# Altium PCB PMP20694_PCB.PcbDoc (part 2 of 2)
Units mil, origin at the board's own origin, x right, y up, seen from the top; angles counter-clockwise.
Board outline 7086.61 x 2677.17 mil, 2 copper layers (Top Layer, Bottom Layer), stack 62 mil thick; 190 components, 99 nets, 453 pads, 121 vias.
Unrouted connection lines stored in the file: 1.
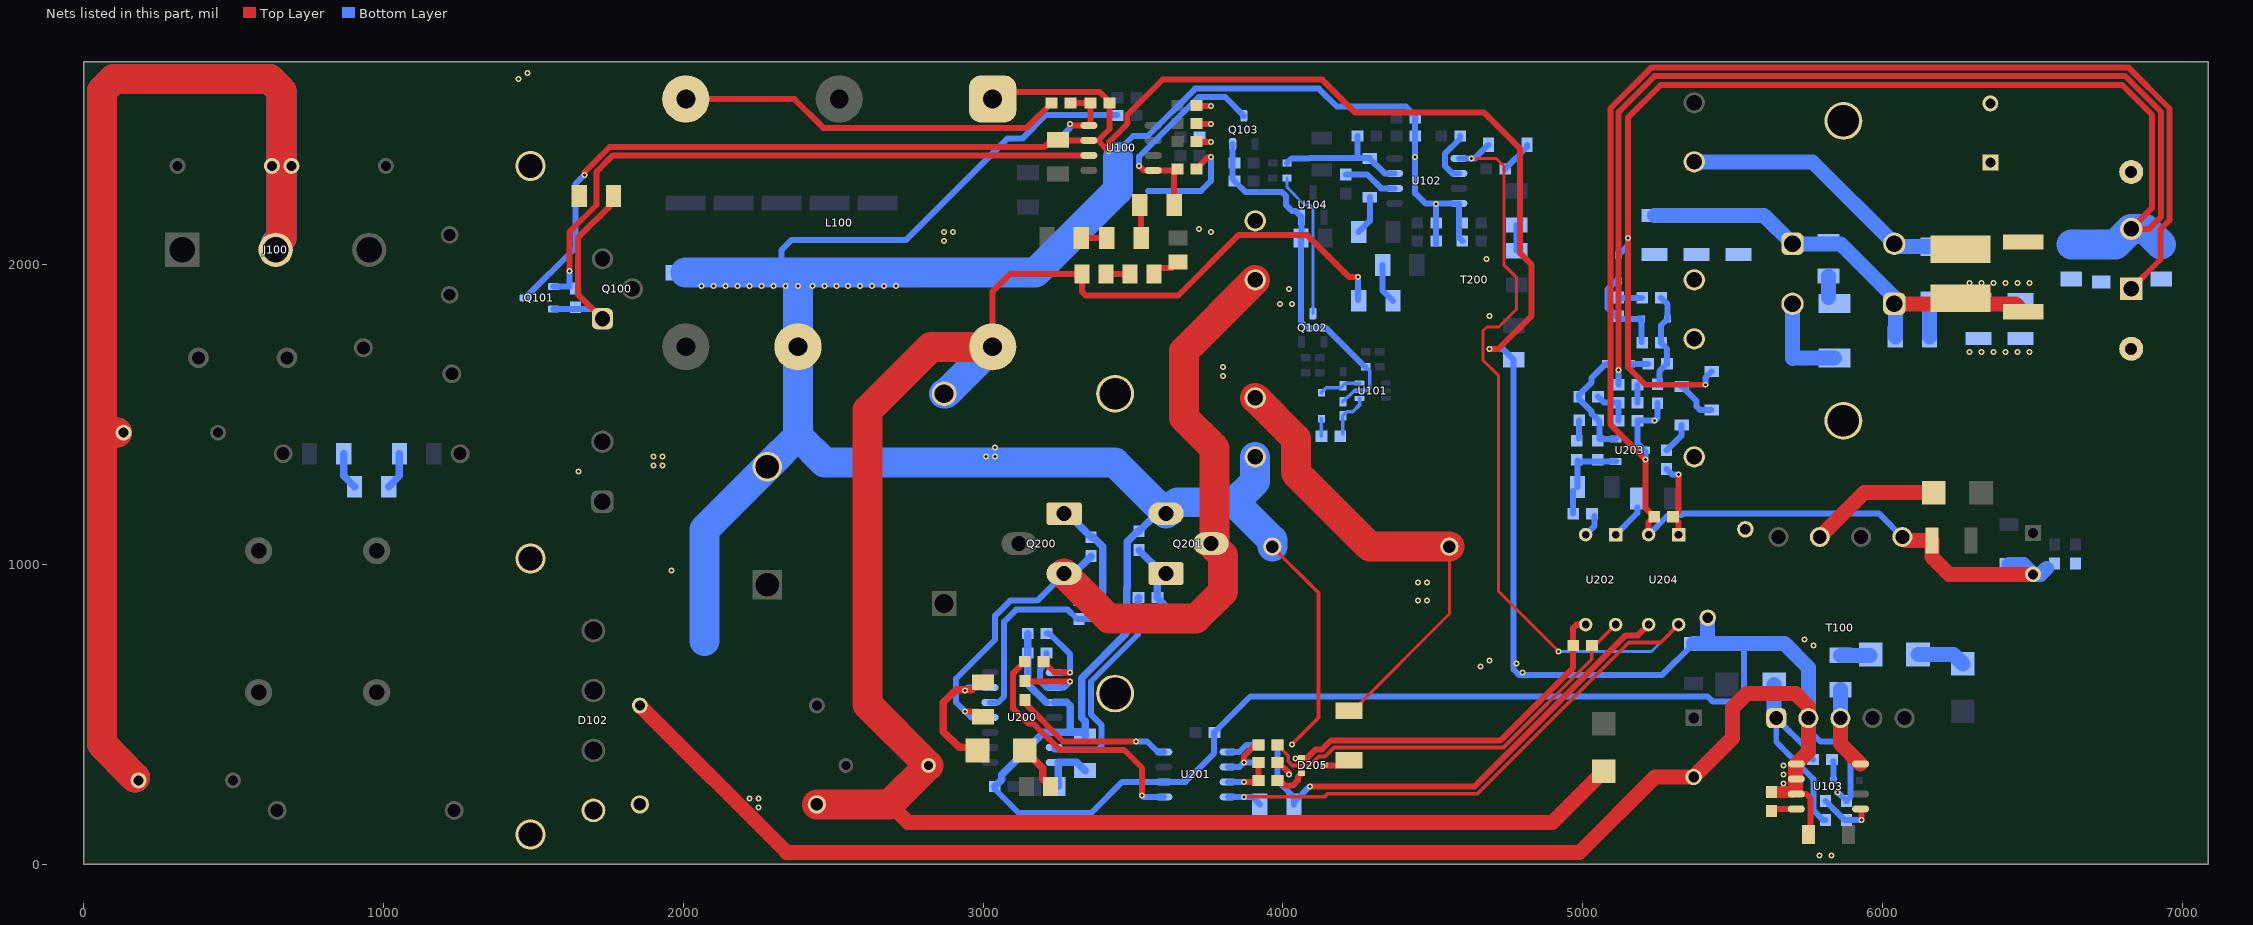
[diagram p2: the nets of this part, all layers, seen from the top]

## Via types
v1: diameter 20, hole 10, Top Layer to Bottom Layer, 118 vias
v2: diameter 100, hole 80, Top Layer to Bottom Layer, 3 vias

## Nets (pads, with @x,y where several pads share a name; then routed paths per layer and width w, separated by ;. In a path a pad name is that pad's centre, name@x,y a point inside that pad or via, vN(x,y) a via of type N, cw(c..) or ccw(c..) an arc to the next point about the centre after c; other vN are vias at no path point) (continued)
NetC201_1: C201.1 D201.1 U200.13 | length 484.3
  Top Layer w25: D201.1@2981.26,380 2971.26,390 2920,390 2867.5,442.5 2867.5,540.03 2909.97,582.5 2962.5,582.5 2987.09,607.09 C201.1@3000,607.09
  Bottom Layer w20: v1(2940,580) 2950,590 U200.13@3022.72,590
NetC201_2: C201.2 Q200.3 Q201.2 R202.1 T200.4 U200.11 | length 2784
  Top Layer w20: v1(2940,510) 2982.91,510 C201.2@3000,492.91 C201.2@3015.75,492.91
  Top Layer w100: Q200.3@3270,970 3420,820 3710,820 3800,910 3800,1030 3772.28,1057.72 3772.28,1387.72 3670,1490 3670,1712.28 T200.4@3907.72,1950
  Bottom Layer w20: U200.11@3022.72,490 2960,490 v1(2940,510) 2910,540 2910,620 3040,750 3040,830 3090,880 3180,880 Q200.3@3270,970
  Bottom Layer w25: Q200.3@3270,970 3301.5,970 R202.1@3360,1028.5
NetC202_1: C202.1 C206.2 C207.2 C208.2 C209.2 C210.2 C216.1 D203.1 D204.1 L200.1 R204.1 | length 1481.8
  Top Layer w50: D203.1@6040,1870 6443.86,1870 R204.1@6470,1843.86
  Bottom Layer w50: C208.2@5240,2164.96 C207.2@5380,2164.96 C206.2@5520,2164.96 5605.04,2164.96 D204.1@5700,2070 5860,2070 6040,1890 D203.1@6040,1870 ; C202.1@6042.91,1760 D203.1@6042.91,1867.09
  other v1: 6290,1940 6330,1940 6370,1940 6410,1940 6450,1940 6490,1940
NetC202_2: C202.2 R206.1 | length 96.5
  Bottom Layer w50: C202.2@6157.09,1760 R206.1@6157.09,1856.54
NetC203_1: C203.1 R203.1 U200.7 | length 168.5
  Bottom Layer w25: R203.1@3250,260 3250,327.28 ; U200.7@3250,340 3312.91,340 C203.1@3340,312.91
NetC205_1: C205.1 R207.1 U200.2 | length 371
  Top Layer w20: R207.1@3140,611.5 3141.5,610 v1(3290,610)
  Bottom Layer w20: C205.1@3211.5,705 3211.5,672.93 3190.87,652.3 3190.87,650.87 3190,650 3190,610.23 3210.23,590 U200.2@3237.28,590 3270,590 v1(3290,610)
NetC213_2: C213.2 R205.1 U200.1 | length 324.4
  Top Layer w20: R205.1@3201.5,676.46 3237.95,640 v1(3290,640)
  Bottom Layer w20: C213.2@3211.5,770 3221.02,770 3290,701.02 v1(3290,640) U200.1@3237.28,640
NetC214_1: C214.1 C215.1 T200.6 | length 1613.5
  Top Layer w10: C214.1@4220,512.68 4232.68,512.68 4555.28,835.28 C215.1@4555.28,1060
  Top Layer w100: T200.6@3907.72,1556.3 4043.15,1420.87 4043.15,1306.85 4290,1060 C215.1@4555.28,1060
NetC214_2: C214.2 D205.3 | length 89.8
  Top Layer w20: D205.3@4137.4,330 4202.68,330 C214.2@4220,347.32
NetC216_2: C216.2 R211.1 | length 72.4
  Bottom Layer w50: R211.1@5820,1890.55 C216.2@5820,1962.91
NetC220_1: C220.1 R213.2 U202.4 | length 1383.9
  Top Layer w12: R213.2@3981.5,398.54 4017.42,362.61 4017.42,343.87 4031.41,329.89 4069.89,329.89 4070,330 4090,330 4120,360 4140.22,360 4170.22,390 4736.24,390 5030,683.76 5030,720 U202.4@5110,800
NetC221_1: C221.1 D208.1 R225.2 R226.1 U203.2 | length 356.9
  Bottom Layer w20: R226.1@4988.5,1560 4988.5,1551.5 5030,1510 5030,1502.99 R225.2@5051.5,1481.5 ; R226.1@4988.5,1567.05 5030,1608.54 5030,1623.31 D208.1@5076.69,1670 ; R225.2@5055.91,1477.09 5055.91,1418.9 U203.2@5110.57,1418.9
NetC221_2: C221.2 C223.2 R216.1 R217.2 U203.1 | length 287.3
  Bottom Layer w20: R217.2@4968.5,1170 R216.1@4968.5,1244.96 ; R216.1@4982.91,1259.37 C223.2@4982.91,1347.09 ; C223.2@4985.91,1344.09 U203.1@5110.57,1344.09
NetC222_1: C222.1 R219.1 | length 77
  Bottom Layer w20: R219.1@5121.5,1890 C222.1@5198.5,1890
NetC222_2: C222.2 D207.2 R223.1 R224.2 R228.2 | length 327.9
  Bottom Layer w20: R228.2@5250,1601.5 5256.06,1607.56 5256.06,1644.57 R224.2@5281.5,1670 5281.5,1720 R223.1@5261.5,1740 5261.5,1798.19 D207.2@5283.31,1820 5283.31,1868.19 C222.2@5261.5,1890
NetC223_1: C223.1 R225.1 | length 60
  Bottom Layer w20: C223.1@4988.5,1421.5 R225.1@4988.5,1481.5
NetC224_1: C224.1 R215.1 R220.2 U201.3 | length 199.7
  Top Layer w20: v1(3870,275) R215.1@3913.5,275 ; R215.1@3918.5,280 C224.1@3918.5,340
  Bottom Layer w20: U201.3@3817.28,275 v1(3870,275) R220.2@3913.5,275
NetD103_1: D103.1 R125.2 U101.3 | length 140.9
  Bottom Layer w12: D103.1@4128.19,1573.31 4144.88,1590 4193.62,1590 R125.2@4200,1596.38 4209.21,1605.59 U101.3@4255.71,1605.59
NetD103_2: D103.2 R123.1 | length 58.3
  Bottom Layer w12: R123.1@4128.19,1428.35 D103.2@4128.19,1486.69
NetD105_2: D105.2 T100.8 | length 441.4
  Top Layer w50: T100.8@5791.1,1092.17 5938.94,1240 D105.2@6171.26,1240
NetD106_1: D106.1 D107.1 | length 162.7
  Bottom Layer w50: D107.1@6118.74,700 6237.24,700 D106.1@6268.5,668.74
NetD107_2: D107.2 R129.1 | length 98.3
  Bottom Layer w50: R129.1@5860,697.09 D107.2@5958.35,697.09
NetD108_2: D108.2 R134.2 | length 64.8
  Bottom Layer w20: D108.2@5836.69,280 R134.2@5836.69,344.8
NetD109_2: D109.2 R134.1 R139.2 T100.1 | length 706
  Bottom Layer w20: R134.1@5768.5,350 5750,368.5 5750,383.66 T100.1@5645.83,487.83 5645.83,408.29 5770,284.11 5770,180 5801.5,148.5 R139.2@5810,148.5
  Bottom Layer w50: T100.1@5638.74,494.92 D109.2@5638.74,600
NetD110_1: D110.1 R131.1 R136.1 U102.7 | length 460.9
  Bottom Layer w20: R136.1@4013.62,2340 4028.09,2354.47 4086.24,2354.47 4088.15,2356.38 4290,2356.38 D110.1@4290,2354.47 4339.47,2305 U102.7@4372.72,2305 ; 4248.5,2357.38 R131.1@4248.5,2430
NetD110_2: D110.2 R145.1 | length 130.9
  Bottom Layer w20: R145.1@4252.91,2110 4290,2147.09 D110.2@4290,2225.53
NetD111_2: D111.2 R146.2 | length 110.2
  Bottom Layer w20: R146.2@4741.5,2320 4814.47,2392.97 D111.2@4814.47,2400
NetD200_1: D200.1 R200.1 U200.12 | length 654.6
  Bottom Layer w20: U200.12@3022.72,540 3050,540 3070,560 3070,810 3110,850 3281.77,850 3313.27,818.5 R200.1@3320,818.5 3372.67,818.5 D200.1@3384.48,806.69
NetD200_2: D200.2 Q200.1 R200.2 R202.2 | length 416.2
  Bottom Layer w20: R200.2@3320,881.5 3372.67,881.5 D200.2@3384.48,893.31
  Bottom Layer w25: Q200.1@3270,1170 3281.5,1170 R202.2@3360,1091.5 3366.65,1091.5 3399.07,1059.07 3399.07,907.9 D200.2@3384.48,893.31
NetD201_2: D201.2 R201.2 | length 155.5
  Top Layer w25: D201.2@3138.74,380 3198.46,320.28 3198.46,285.94 R201.2@3224.41,260
NetD202_1: D202.1 R208.1 U200.6 | length 744.2
  Bottom Layer w20: U200.6@3237.28,390 3237.28,383.62 3383.82,383.62 3394.29,394.09 3394.29,465.71 3359.13,500.87 3359.13,604.36 3360,605.23 3360,610 3516.69,766.69 D202.1@3516.69,820
  Bottom Layer w25: D202.1@3516.69,820 3516.69,888.19 R208.1@3518.5,890
NetD202_2: D202.2 Q201.1 R208.2 R209.1 | length 253
  Bottom Layer w25: R209.1@3520,1048.5 3598.5,970 Q201.1@3610,970 ; Q201.1@3581.5,941.5 R208.2@3581.5,890 3603.31,868.19 D202.2@3603.31,820
NetD203_3: D203.3 R206.2 T200.13 | length 911.6
  Bottom Layer w50: T200.13@5372.28,2343.7 5766.3,2343.7 D203.3@6040,2070 ; D203.3@6049.45,2060.55 R206.2@6180,2060.55
NetD204_3: D204.3 R211.2 T200.8 | length 320.6
  Bottom Layer w50: 5700,1687.17 D204.3@5700,1870 ; 5702.28,1689.45 R211.2@5840,1689.45
NetD206_2: D206.2 D207.1 R219.2 R223.2 | length 316.8
  Bottom Layer w20: D206.2@5120,1946.69 5111.53,1946.69 5083.43,1918.58 5083.43,1856.57 5120,1820 D207.1@5196.69,1820 R223.2@5196.69,1741.81
NetD208_2: D208.2 R224.1 | length 55.2
  Bottom Layer w20: D208.2@5163.31,1670 R224.1@5218.5,1670
NetD209_1: D209.1 D210.2 | length 142.6
  Bottom Layer w20: D209.1@5330,1594.47 5380,1544.47 5380,1527.5 5391.97,1515.53 D210.2@5430,1515.53
NetD209_2: D209.2 R229.2 | length 104.7
  Bottom Layer w20: R229.2@5280,1381.5 5330,1431.5 D209.2@5330,1465.53
NetQ100_1: Q100.1 Q101.2 R103.2 R105.2 | length 669.7
  Top Layer w20: Q100.1@1730,1820 1647.87,1902.13 1647.87,2090 1767.09,2209.21 R105.2@1767.09,2230
  Bottom Layer w20: Q101.2@1567.24,1852.6 1697.4,1852.6 Q100.1@1730,1820
NetQ101_1: Q101.1 R103.1 U100.7 | length 2138.1
  Top Layer w20: v1(1620,1980) 1620,2109.8 1710,2199.8 1710,2310 1765,2365 U100.7@3352.72,2365
  Bottom Layer w20: Q101.1@1567.24,1927.4 1620,1927.4 v1(1620,1980)
NetQ102_3: Q102.3 R132.2 | length 498.9
  Bottom Layer w10: R132.2@4013.62,2290 4013.62,2258.73 4072.35,2200 4090,2200 4100,2190 Q102.3@4100,1837.24
NetR100_1: R100.1 R102.2 | length 124.8
  Bottom Layer w25: R102.2@1017.09,1260 1052.91,1295.83 R100.1@1052.91,1370
NetR102_1: R102.1 R104.2 | length 124.8
  Bottom Layer w25: R104.2@867.09,1370 867.09,1295.83 R102.1@902.91,1260
NetR111_1: R111.1 R112.2 | length 105.8
  Top Layer w20: R112.2@3527.09,2090 R111.1@3527.09,2195.83
NetR112_1: R112.1 R113.2 | length 85.8
  Top Layer w20: R113.2@3327.09,2090 R112.1@3412.91,2090
NetR114_1: R114.1 R115.2 | length 80
  Top Layer w20: R114.1@3410,1970 R115.2@3490,1970
NetR115_1: R115.1 R116.2 | length 96.6
  Top Layer w20: R115.1@3570,1970 3590,1990 3630,1990 R116.2@3650,2010
NetR123_2: R123.2 R124.2 U101.1 | length 152.4
  Bottom Layer w12: R123.2@4200,1436.54 R124.2@4200,1496.38 4213.62,1510 4233.15,1510 4255.71,1532.56 U101.1@4255.71,1554.41
NetR127_1: R127.1 R133.2 | length 85.8
  Bottom Layer w20: R127.1@4780,2047.09 R133.2@4780,2132.91
NetR128_1: R128.1 R135.2 | length 134.2
  Bottom Layer w20: R135.2@4332.91,2000 4332.91,1914.17 R128.1@4367.09,1880
NetR129_2: R129.2 T100.3 U103.8 | length 275.8
  Top Layer w50: T100.3@5860,487.83 5860,402.28 U103.8@5927.28,335
  Bottom Layer w50: T100.3@5860,487.83 R129.2@5860,582.91
NetR130_1: R130.1 U102.6 | length 182
  Bottom Layer w20: R130.1@4210,2301.5 4281.34,2301.5 4327.84,2255 U102.6@4372.72,2255
NetR137_1: R137.1 U102.2 | length 179
  Bottom Layer w20: U102.2@4587.28,2305 4565,2305 4540,2330 4540,2370 4591.5,2421.5 R137.1@4591.5,2430
NetR139_1: R139.1 R143.2 U103.5 | length 180.3
  Top Layer w20: v1(5930,148.5) U103.5@5930,182.28
  Bottom Layer w20: R139.1@5810,211.5 5810.67,211.5 5846.57,175.59 5846.57,174.92 5872.99,148.5 R143.2@5880,148.5 v1(5930,148.5)
NetR144_2: R144.2 U103.4 | length 85.4
  Top Layer w20: R144.2@5630,178.5 5636.5,185 U103.4@5712.72,185
NetR205_2: R205.2 U201.5 | length 851.3
  Top Layer w20: R205.2@3138.5,676.46 3100,637.95 3100,520 3150,470 3167.53,470 3255.4,382.13 3470,382.13 3530,322.13 v1(3530,230)
  Bottom Layer w20: v1(3530,230) 3535,225 U201.5@3602.72,225
NetR207_2: R207.2 U201.8 | length 541.4
  Top Layer w20: R207.2@3140,548.5 3140,536.95 3266.95,410 v1(3510,410)
  Bottom Layer w20: v1(3510,410) 3547.36,410 3582.36,375 U201.8@3602.72,375
NetR212_1: R212.1 U202.1 | length 120.2
  Bottom Layer w20: U202.1@5110,1100 5182.91,1172.91 R212.1@5182.91,1190
NetR213_1: R213.1 R222.2 U201.2 | length 181.9
  Top Layer w20: v1(3870,340) 3870,359.98 R213.1@3908.56,398.54
  Bottom Layer w20: U201.2@3817.28,325 3855,325 v1(3870,340) R222.2@3918.5,340
NetR214_1: R214.1 R218.2 | length 60
  Bottom Layer w20: R218.2@5183.31,1540 R214.1@5183.31,1600
NetR217_1: R217.1 U202.2 | length 73.9
  Bottom Layer w20: U202.2@5010,1100 5040,1130 R217.1@5040,1161.5
NetR218_1: R218.1 R226.2 R227.2 | length 137.1
  Bottom Layer w20: R226.2@5051.5,1560 5071.5,1540 R218.1@5120.31,1540 R227.2@5120.31,1480
NetR221_2: R221.2 U201.1 | length 111
  Bottom Layer w20: U201.1@3817.28,375 3855,375 3878.54,398.54 R221.2@3918.5,398.54
NetR229_1: R229.1 R230.2 U204.1 | length 263
  Top Layer w20: U204.1@5320,1100 5320,1141.5 R230.2@5301.5,1160 5320,1178.5 v1(5320,1300)
  Bottom Layer w20: R229.1@5280,1318.5 5298.5,1300 v1(5320,1300)
PE: C100.1 C101.1 C108.2 C109.2 J100.2 | length 7102.5
  Top Layer w100: 70,1440 C101.1@110,1440 ; C109.2@170,290 60,402.52 60,2580 100,2620 620,2620 660,2580 660,2090 650,2080 650,2070 640,2060 J100.2@640,2050
  Bottom Layer w100: C101.1@110,1440 60,1440 ; C109.2@170,290 60,402.52 60,1440 ; J100.2@640,2050 640,2070 660,2090 660,2580 620,2620 100,2620 60,2580 60,1440
PGND: C105.2 C106.2 C107.2 C110.2 C111.2 C112.2 C113.2 C114.2 C115.2 C116.2 C118.2 C124.2 C125.2 C126.2 C127.1 C128.2 C129.2 C130.2 C131.2 C132.2 C200.1 C203.2 C205.2 C213.1 C215.2 C217.2 C218.2 C219.2 C220.2 C224.2 D102.4 D205.1 H200.1 H200.2 L100.1 L100.7 Q101.3 Q103.2 Q201.3 R105.1 R106.1 R107.1 R108.1 R109.1 R110.1 R120.1 R121.1 R124.1 R140.1 R141.1 R142.1 R143.1 R144.1 R209.2 R220.1 R221.1 R222.1 T100.2 T200.7 U100.6 U101.2 U102.4 U103.1 U103.2 U103.3 U104.2 U200.3 U200.5 U201.6 U202.3 U204.3 | length 31190.2
  Top Layer w12: C215.2@3964.72,1060 4118.72,906 4118.72,488.72 v1(4030,400)
  Top Layer w20: v1(1670,2300) 1670,2309.42 1753.45,2392.87 3203.74,2392.87 3225.87,2415 U100.6@3352.72,2415 3383.31,2415 ; L100.1@3031.81,2553.39 3055,2576.57 3388.57,2576.57 3421.5,2543.65 C113.2@3421.5,2540 3421.5,2453.19 3383.31,2415 ; v1@3419.15,2379.15 3383.31,2415 ; v1(3420,2380) 3420,2409.42 3482.13,2471.55 3482.13,2501.55 3598.45,2617.87 4131.55,2617.87 4241.55,2507.87 4671.55,2507.87 4791.5,2387.92 4791.5,2038.5 4830,2000 4830,1830.58 4719.42,1720 v1(4690,1720) ; R121.1@3711.5,2320 3751.5,2360 v1(3760,2360) ; C112.2@3712.95,2410 v1(3760,2410) ; R120.1@3712.95,2470 v1(3760,2470) ; C110.2@3712.95,2530 v1(3760,2530) ; C224.2@3981.5,340 3985.16,340 4020,305.16 v1(4020,300) ; D205.1@4062.6,355.59 4081.83,355.59 4110.11,383.87 4130.33,383.87 4160.33,413.87 4726.35,413.87 4968.5,656.03 C220.2@4968.5,730 4968.5,788.5 4980,800 U202.3@5010,800 ; v1(4090,260) 4640,260 5143.87,763.87 5183.87,763.87 U204.3@5220,800 ; U103.3@5712.72,235 5745,235 5760,220 C127.1@5760,106.93
  Top Layer w39.37: R144.1@5630,241.5 5701.5,241.5 5710,250
  Top Layer w50: C105.2@1854.72,530 2344.72,40 4990,40 5241.57,291.57 C118.2@5370,291.57 5500,421.57 5500,521.5 5548.5,570 5710,570 5752.91,527.09 T100.2@5752.91,487.83 5752.91,375.2 U103.1@5712.72,335 5710,332.28 5710,250
  Bottom Layer w12: R124.1@4200,1543.62 4216.38,1560 4218.23,1560 4238.23,1580 U101.2@4255.71,1580 4280,1580 4290,1590 4290,1646.38 C116.2@4276.38,1660
  Bottom Layer w20: Q101.3@1472.76,1890 1640,2057.24 1640,2270 v1(1670,2300) ; R108.1@2327.01,1973.86 2327.01,2049.13 2360,2082.13 2741.55,2082.13 3081.55,2422.13 3131.55,2422.13 3209.3,2499.88 C115.2@3446.38,2499.88 ; C200.1@3038.5,260 3038.5,251.5 3117.87,172.13 3361.55,172.13 3464.42,275 U201.6@3602.72,275 3675,275 3770.87,370.87 3770.87,439.37 C218.2@3771.5,440 3891.5,560 5417.24,560 5434.49,542.76 5528.03,542.76 5538.5,553.23 5538.5,735.43 5540,736.93 ; 3450,2380 3500,2430 3549.42,2430 3707.29,2587.87 4120,2587.87 4179.64,2528.23 4410,2528.23 4441.5,2496.73 C128.2@4441.5,2490 C124.2@4441.5,2430 4441.5,2238.5 4475,2205 v1@4510,2205 ; 3550,2246.26 3726.26,2246.26 3760,2280 v1(3760,2360) ; C125.2@3832.6,2285.91 Q103.2@3832.6,2402.76 ; C125.2@3838.5,2280 3838.5,2279.33 3874.41,2243.43 3996.57,2243.43 4010,2230 4010,2200 4030,2180 4041.26,2180 U104.2@4062.6,2158.66 C131.2@4062.6,2095.91 ; R221.1@3981.5,398.54 R220.1@3981.5,280 4037.09,224.41 C219.2@4037.09,207.09 ; C219.2@4037.09,200 C219.2@4037.09,207.09 ; C131.2@4060,2090 4060,1810 4080,1790 4143.47,1790 4273.47,1660 C116.2@4276.38,1660 ; v1(4090,260) C219.2@4037.09,207.09 ; R141.1@4511.5,2070 v1(4511.5,2203.5) v1@4510,2205 ; R142.1@4598.5,2080 4587.28,2091.22 U102.4@4587.28,2205 v1@4510,2205 ; v1(4690,1720) 4732.91,1720 C129.2@4770,1682.91 4770,650 4789.06,630.94 5264.02,630.94 C130.2@5370,736.93 ; T100.2@5752.91,487.83 5752.91,450 5792.91,410 5870,410 5893.62,386.38 5893.62,225.12 R143.1@5880,211.5 5851.5,240 v1(5850,240)
  Bottom Layer w25: C200.1@3038.5,260 3061.44,282.93 3061.44,299.07 3202.36,440 U200.5@3237.28,440 3290,440 ; C213.1@3148.5,770 C205.2@3148.5,705 3148.5,601.5 U200.3@3210,540 ; U200.3@3237.28,540 3279.34,540 3290,529.34 3290,440 ; C203.2@3327.09,440 3290,440 ; C203.2@3340,427.09 3340,477.04 3328.76,488.28 3328.76,621.72 3475.88,768.83 3475.88,773.88 3478.44,776.45 3478.44,919.62 3480.93,922.1 3480.93,1076.72 3515.7,1111.5 R209.2@3520,1111.5 3578.5,1170 Q201.3@3610,1170
  Bottom Layer w50: C130.2@5370,736.93 5540,736.93 5673.07,736.93 5752.91,657.09 T100.2@5752.91,487.83 ; 5417.01,739.92 C217.2@5417.01,822.36
  Bottom Layer w100: R107.1@2007.01,1973.86 R106.1@2167.01,1973.86 R108.1@2327.01,1973.86 R110.1@2487.01,1973.86 R109.1@2647.01,1973.86 3173.86,1973.86 3450,2250 3450,2360 ; 2070,745.28 2070,1116.85 C107.2@2280,1326.85 2382.2,1429.06 ; R108.1@2382.2,1956.06 L100.7@2382.2,1726.61 2382.2,1429.06 ; T200.7@3907.72,1359.45 3907.72,1277.5 3838.22,1208 ; C215.2@3964.72,1060 3964.72,1081.49 3838.22,1208 ; 2382.2,1429.06 2471.26,1340 3440,1340 Q201.3@3610,1170 3648,1208 3838.22,1208
  other v1: 5790,30 5830,30 2250,190 2220,220 2250,220 5670,270 5670,300 5670,330 4041.3,353.76 4800,640 4660,660 4780,670 4690,680 5770,730 5740,750 4450,880 4480,880 4450,940 4480,940 1960,980 1650,1310 1900,1330 1930,1330 1900,1360 1930,1360 3010,1360 3040,1360 3040,1390 3800,1630 3800,1660 4690,1830 3990.39,1870 4030,1870 4020,1920 2060,1930 2100,1930 2140,1930 2180,1930 2220,1930 2260,1930 2300,1930 2340,1930 2382.2,1930 2430,1930 2470,1930 2510,1930 2550,1930 2590,1930 2630,1930 2670,1930 2710,1930 4680,2020 2870,2080 2870,2110 2900,2110 3760,2110 3720,2120 4440,2360 1450,2620 1480,2640
  other v2: 1490,100 1490,1020 1490,2330
SGND: C119.2 C120.1 C121.2 C122.2 C123.2 C204.2 C206.1 C207.1 C208.1 C209.1 C210.1 C211.2 C212.2 C217.1 H201.1 H201.2 J200.1 R210.1 R227.1 R228.1 R230.1 T100.6 T200.10 T200.11 TP201.1 U203.3 U204.2 | length 5949.2
  Top Layer w20: U204.2@5220,1100 5220,1141.5 R230.1@5238.5,1160 5210,1188.5 v1(5210,1350) 5092.13,1467.87 5092.13,2521.55 5228.45,2657.87 6821.55,2657.87 6957.87,2521.55 6957.87,2148.45 6927.87,2118.45 6927.87,2017.87 J200.1@6830,1920
  Top Layer w50: T100.6@6066.69,1092.17 6078.86,1080 C120.1@6165.04,1080 6165.04,1024.96 6222.25,967.75 C119.2@6502.62,967.75
  Bottom Layer w20: U203.3@5205.06,1381.5 5183.31,1403.24 R227.1@5183.31,1480 v1(5240,1480) 5250,1490 R228.1@5250,1538.5 ; v1(5210,1350) U203.3@5210,1376.55 ; U204.2@5220,1100 5282.13,1162.13 5308.63,1162.13 5312.22,1165.71 5330.08,1165.71 5334.37,1170 5988.86,1170 T100.6@6066.69,1092.17
  Bottom Layer w50: C123.2@6422.62,999.72 6470.65,999.72 C119.2@6502.62,967.75 6527.75,967.75 6546.65,986.65
  other v1: 6290,1710 6330,1710 6370,1710 6410,1710 6450,1710 6490,1710
SS: C219.1 D111.1 U102.1 U201.4 U204.4 | length 4289.1
  Top Layer w10: v1(4630,2355) 4712.13,2355 4737.13,2330 4737.13,2000 4777.13,1960 4779.25,1960 4779.25,1851.6 4720.53,1792.87 4680.53,1792.87 4667.13,1779.47 4667.13,1682.87 4720,1630 4720,910 v1(4920,710)
  Top Layer w12: v1(3870,225) 4138.87,225 4150,236.13 4649.89,236.13 5153.76,740 5260,740 U204.4@5320,800
  Bottom Layer w10: v1(4920,710) 5230,710 U204.4@5320,800
  Bottom Layer w20: U201.4@3817.28,225 v1(3870,225) 3897.91,225 C219.1@3922.91,200 ; U102.1@4587.28,2355 v1(4630,2355) 4640.53,2355 D111.1@4685.53,2400
VCS: D205.2 R215.2 | length 112.8
  Top Layer w20: R215.2@3981.5,280 3989.98,280 4007.63,262.35 4032.35,262.35 4050,280 4050,291.81 D205.2@4062.6,304.41
VOUT: C204.1 C211.1 C212.1 D206.1 D210.1 J200.2 L200.2 R204.2 R210.2 R214.2 TP200.1 | length 7111.7
  Top Layer w20: v1(5120,1650) 5120,2510 5240,2630 6810,2630 6930,2510 6930,2160 6890,2120 J200.2@6830,2120 6900,2190 6900,2500 6800,2600 5260,2600 5151.81,2491.81 v1(5151.81,2090) 5151.81,1657.69 5209.5,1600 v1(5410,1600)
  Bottom Layer w20: R214.2@5120,1600.32 v1(5120,1650) ; D206.1@5120,2033.31 5151.81,2065.12 v1(5151.81,2090) ; v1(5410,1600) 5410,1624.47 D210.1@5430,1644.47
  Bottom Layer w100: R210.2@6630,2067.09 6777.09,2067.09 J200.2@6830,2120 6877.09,2120 C211.1@6930,2067.09
VREC: C106.1 D100.2 D104.2 L100.8 L101.2 R114.2 R128.2 T200.3 | length 6615.3
  Top Layer w20: L100.8@3031.81,1726.61 3031.81,1911.81 3090,1970 R114.2@3330,1970 3330,1955 3330,1910 3341.5,1898.5 3651.57,1898.5 3853.07,2100 4080,2100 4220,1960 v1(4250,1960)
  Top Layer w50: 2687.8,200 2690,200 2750,140 4898.74,140 D104.2@5070,311.26
  Top Layer w100: C106.1@2445.28,200 2687.8,200 L101.2@2817.8,330 2615,532.8 2615,1515 2826.61,1726.61 L100.8@3031.81,1726.61
  Bottom Layer w20: R128.2@4250,1882.91 v1(4250,1960)
  Bottom Layer w100: D100.2@2870,1570 2875.2,1570 L100.8@3031.81,1726.61
VSNS: Q103.3 R111.2 R121.2 U100.1 | length 700.8
  Top Layer w20: v1(3520,2330) 3535,2315 U100.1@3567.28,2315 R121.2@3643.5,2315 ; R111.2@3637.09,2230 R121.2@3637.09,2308.58
  Bottom Layer w20: v1(3520,2330) 3520,2361.16 3718.84,2560 3807.24,2560 Q103.3@3870,2497.24 Q103.3@3867.01,2497.24
ZCD: L100.5 R117.1 | length 1294.8
  Top Layer w12: L100.5@2008.19,2553.39 L100.5@2040,2553.39
  Top Layer w20: L100.5@2040,2553.39 2370,2553.39 2466.61,2456.77 3145.28,2456.77 R117.1@3228.5,2540
ZCD1: C113.1 R101.1 R117.2 U100.5 | length 270.5
  Top Layer w20: v1(3290,2470) 3295,2465 U100.5@3352.72,2465 ; R117.2@3291.5,2540 C113.1@3358.5,2540 U100.5@3358.5,2470.79
  Bottom Layer w20: R101.1@3250,2417.09 3290,2457.09 v1(3290,2470)
pads on no net: L100.3 T100.4 T100.7 T100.9 T200.14 U101.5 U104.3 U200.4 U200.8 U200.9 U200.10 U200.14

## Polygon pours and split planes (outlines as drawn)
NetC103_2 on Top Layer "C103_2" (solid, remove dead copper, pour order 2): 640,1740 590,1690 590,1660 590,1540 590,1200 530,1140 530,1070 530,1010 550,990 580,990 750,990 770,1010 770,1060 770,1230 935,1395 935,1525 770,1690 720,1740
NetC108_1 on Top Layer "C108_1" (solid, remove dead copper, pour order 0): 280,2100 280,1890 280,1680 350,1610 390,1570 430,1570 570,1570 580,1580 580,1600 580,1700 630,1750 650,1750 750,1750 800,1700 830,1670 950,1670 960,1670 980,1690 980,1760 890,1850 830,1850 530,1850 400,1980 400,2060 400,2090 390,2100
NetC101_2 on Top Layer "C101_2" (solid, remove dead copper, pour order 10): 880,630 850,600 850,570 850,260 980,130 1050,60 1110,60 1190,60 1290,160 1650,520 1680,520 1730,520 1750,540 1750,580 1750,610 1730,630
NetC105_1 on Top Layer "C105_1" (solid, remove dead copper, pour order 12): 1650,730 1630,750 1630,780 1630,830 1650,850 1710,910 1820,910 2050,910 2180,780 2200,760 2390,760 2500,650 2550,600 2550,510 2590,470 2620,440 2620,320 2620,300 2600,280 2504.33,280 2290,280 1840,730
VREC on Top Layer "VREC" (solid, remove dead copper, pour order 14): 2340,270 2320,250 2320,210 2320,160 2320,140 2340,120 2380,120 2420,120 2504.33,120 2850,120 2870,140 2870,210 2870,370 2830,410 2820,420 2820,590 2780,630 2780,910 2780,1360 3110,1690 3120,1700 3120,1760 3120,1780 3100,1800 3080,1820 3010,1820 2790,1820 2490,1520 2490,1420 2490,420 2340,270
NetC102_1 on Top Layer "C102_1" (solid, remove dead copper, pour order 16): 1810,1960 1790,1940 1790,1900 1900,1790 1900,1740 1900,1650 1690,1440 1690,1400 1690,1380 1710,1360 1750,1360 1810,1360 2090,1640 2090,1700 2090,1790 1920,1960
B+ on Top Layer "B+" (solid, remove dead copper, pour order 18): 1710,1260 1690,1240 1690,1200 1690,1160 1690,1070 1710,1050 1990,1050 2170,870 2230,810 2310,810 2390,810 2410,830 2410,850 2410,960 2110,1260
NetD204_3 on Top Layer "D204_3" (solid, remove dead copper, pour order 24): 5750,1920 5770,1900 5770,1860 5770,1520 5570,1320 5390,1320 5340,1320 5320,1340 5320,1360 5320,1440 5520,1640 5520,1780 5660,1920
NetC202_1 on Top Layer "C202_1" (solid, remove dead copper, pour order 28): 6010,1960 5990,1940 5990,1890 5990,1810 6010,1790 6052.76,1790 6530,1790 6550,1810 6550,1850 6550,1940 6530,1960
VOUT on Top Layer "Vout" (solid, remove dead copper, pour order 32): 6160,1990 6140,2010 6140,2040 6140,2230 6140,2250 6270,2380 6310,2380 6860,2380 6880,2360 6880,2330 6880,2010 6860,1990
NetD105_2 on Top Layer "D105_2" (solid, remove dead copper, pour order 34): 5760,1050 5740,1070 5740,1090 5740,1140 5740,1190 5860,1310 6200,1310 6220,1290 6220,1260 6220,1200 6200,1180 6130,1180 5920,1180 5850,1110 5830,1090 5830,1070 5810,1050
12V on Top Layer "12V" (solid, remove dead copper, pour order 36): 6280,1030 6260,1050 6260,1060 6260,1270 6260,1290 6278.9,1308.9 6280,1308.9 6371.1,1308.9 6540,1140 6540,1110 6540,1050 6520,1030
PGND on Top Layer "PGND" (solid, remove dead copper, pour order 44): 1450,10 1430,30 1430,50 1430,120 1520,210 1540,230 1550,230 1690,230 1760,230 1790,230 1820,260 1820,310 1820,670 1570,920 1460,920 1450,920 1430,940 1430,960 1430,1110 1450,1130 1480,1130 1570,1130 1570,2210 1520,2260 1460,2260 1450,2260 1430,2280 1430,2310 1430,2640 1450,2660 1490,2660 4780,2660 4800,2640 4800,2610 4800,920 4890,830 4910,830 5460,830 5520,770 5570,770 5850,770 5870,750 5870,720 5870,30 5850,10
SGND on Top Layer "SGND" (solid, remove dead copper, pour order 48): 4950,1070 4930,1090 4930,1120 4930,1500 4930,1980 5050,2100 5050,2150 5050,2640 5078.5,2668.5 7051.5,2668.5 7080,2640 7080,2610 7080,920 7060,900 7050,900 6180,900 6020,1060 4960,1060
NetC108_1 on Bottom Layer "C108_1" (solid, remove dead copper, pour order 4): 280,2100 280,1890 280,1680 350,1610 390,1570 430,1570 570,1570 580,1580 580,1600 580,1700 630,1750 650,1750 750,1750 800,1700 830,1670 950,1670 960,1670 980,1690 980,1760 890,1850 830,1850 530,1850 400,1980 400,2060 400,2090 390,2100
NetC103_2 on Bottom Layer "C103_2" (solid, remove dead copper, pour order 6): 640,1740 590,1690 590,1660 590,1540 590,1200 530,1140 530,1070 530,1010 550,990 580,990 750,990 770,1010 770,1060 770,1230 780,1240 780,1680 770,1690 720,1740
NetC104_2 on Bottom Layer "C104_2" (solid, remove dead copper, pour order 8): 500,60 470,90 470,110 470,340 470,600 500,630 520,630 730,630 760,600 760,550 760,460 790,430 810,430 1730,430 1750,410 1750,400 1750,320 1730,300 1720,300 1170,300 1030,160 930,60
CS on Bottom Layer "CS" (solid, remove dead copper, pour order 20): 1710,1980 1690,2000 1690,2020 1690,2120 1690,2240 1850,2400 1860,2410 1930,2410 2400,2410 2700,2410 2720,2390 2720,2310 2720,2170 2700,2150 2670,2150 1920,2150 1750,1980
B+ on Bottom Layer "B+" (solid, remove dead copper, pour order 22): 3180,1090 3160,1110 3140,1130 3070,1130 3040,1100 3010,1100 2330,1100 2220,990 2220,900 2220,870 2270,820 2330,820 2910,820 2940,850 3040,950 3090,950 3180,1040
NetD203_3 on Bottom Layer "D203_3" (solid, remove dead copper, pour order 26): 5330,2290 5310,2310 5310,2420 5310,2440 5310,2450 5330,2470 5450,2470 5780,2470 6100,2150 6220,2150 6240,2130 6240,2070 6240,2030 6220,2010 6210,2010 6030.91,2010 5820.9,2220 5760,2220 5690,2290
NetC202_1 on Bottom Layer "C202_1" (solid, remove dead copper, pour order 30): 5200,2130 5180,2150 5180,2260 5200,2280 5210,2280 5680,2280 5750,2210 5790,2210 5820,2210 6020,2010 6030,2000 6050,2000 6060,2000 6500,2000 6520,1980 6520,1870 6500,1850 6290,1850 6270,1870 6270,1900 6240,1930 6114.66,1930 6090,1905.33 6090,1720 6070,1700 6050,1700 6010,1700 5930,1780 5930,1860 5930,1950 5850,2030 5839.09,2030 5760,2030 5740,2010 5700,2010 5670,2010 5550,2130
NetD106_1 on Bottom Layer "D106_1" (solid, remove dead copper, pour order 38): 6090,620 6070,640 6070,641.5 6070,670 6070,750 6071.1,750 6090,768.9 6091.1,770 6110,770 6330,770 6350,750 6350,740 6350,640 6330,620
NetC118_1 on Bottom Layer "C118_1" (solid, remove dead copper, pour order 40): 6350,560 6330,580 6320,580 6199.6,580 6100,580 6030,510 6030,490 6030,450 6050,430 6330,430 6350,450
NetD107_2 on Bottom Layer "D107_2" (solid, remove dead copper, pour order 42): 5830,650 5820,660 5820,750 5830,760 5840,760 6000,760 6010,750 6010,740 6010,660 6000,650
PGND on Bottom Layer "PGND" (solid, remove dead copper, pour order 46): 1450,10 1430,30 1430,50 1430,120 1520,210 1540,230 1550,230 1690,230 1760,230 1790,230 1820,260 1820,310 1820,670 1570,920 1460,920 1450,920 1430,940 1430,960 1430,1110 1450,1130 1480,1130 1570,1130 1570,2210 1520,2260 1460,2260 1450,2260 1430,2280 1430,2310 1430,2640 1450,2660 1490,2660 4780,2660 4800,2640 4800,2610 4800,920 4890,830 4910,830 5460,830 5520,770 5570,770 5759.13,770 5870,659.13 5870,30 5850,10
SGND on Bottom Layer "SGND" (solid, remove dead copper, pour order 50): 4950,1070 4930,1090 4930,1120 4930,1500 4930,1980 5050,2100 5050,2150 5050,2640 5078.5,2668.5 7051.5,2668.5 7080,2640 7080,2610 7080,920 7060,900 7050,900 6180,900 6020,1060 4960,1060

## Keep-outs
Keep-Out Layer:
  text ".Layer_Name" at 577,-858.49 h60

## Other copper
Top Layer:
  text ".Layer_Name" at 577,-858.49 h60
Bottom Layer:
  text ".Layer_Name" at 577,-858.49 h60

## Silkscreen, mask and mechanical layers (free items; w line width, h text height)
Top Overlay:
  lines w7: 1490,0 1490,2600 1590,2600 1590,0 1490,0
  text "PMP20694 RevA" at 6290,60 h108.27
  text ".Layer_Name" at 577,-858.49 h60
Bottom Overlay:
  lines w10: 3815,2025 3860,2070 3990,2070 ; 4200,1690 4200,1740 4240,1780 4350,1780 ; 4240,1510 4270,1480 4270,1410 ; 5390,1440 5490,1340 6050,1340 ; 3040,1860 3220,1680 3850,1680 3850,1690 3850,1990 3780,2060 3080,2060 3040,2020 3040,1860 ; 6050,1180 6050,1550 6170,1670 6470,1670 6520,1620 6520,1290 6420,1190 6270,1190 6210,1130 6100,1130 6050,1180
  text ".Layer_Name" at 577,-858.49 h60
Top Paste:
  text ".Layer_Name" at 577,-858.49 h60
Bottom Paste:
  text ".Layer_Name" at 577,-858.49 h60
Top Solder:
  text ".Layer_Name" at 577,-858.49 h60
  text ".Layer_Name" at 577,-858.49 h60
Bottom Solder:
  text ".Layer_Name" at 577,-858.49 h60
Drill Guide:
  text ".Layer_Name" at 577,-858.49 h60
M1 Board Outline:
  the board outline again, w7.01
  text ".Layer_Name" at 577,-858.49 h60
M2 Board Dimensions:
  rectangle: 125,-400 500,-275
  rectangle: 0,-275 125,-150
  lines w7: 0,-275 1000,-275 ; 125,-400 125,-150 ; 250,-400 250,-150 ; 500,-400 500,-150 ; 750,-400 750,-150 ; 0,-400 0,-150 1000,-150 1000,-400 0,-400
  text ".Layer_Name" at 577,-858.49 h60
M3 3D STEP Top:
  text ".Layer_Name" at 577,-858.49 h60
M4 3D STEP Bottom:
  text ".Layer_Name" at 577,-858.49 h60
M5 Assembly Top:
  lines w10: -292,-930.17 6308,-930.17 ; -292,-726.83 6310,-726.83 ; -292,-523.5 -292,-1133.5 3713,-1133.5 6310,-1133.5 6310,-523.5 -291.5,-523.5 -291.5,-1133.5 1284,-1133.5 ; 2173,-1133.5 2173,-523.5 ; 3440,-726.83 3440,-523.5 ; 4280,-726.83 4280,-523.5 ; 4902,-1140 4902,-937.17
  text "COMPONENTS MARKED 'DNP' SHOULD NOT BE POPULATED." at 1153.5,-318.5 h60
  text "ASSEMBLY VARIANT:" at 1153,-434 h60
  text ".VariantName" at 2189,-434 h60
  text "PCB VIEWED FROM TOP SIDE" at -228.5,-655.67 h60
  text "BOARD #:" at 2248,-655.67 h60
  text ".PRJ_Number" at 2793.5,-655.67 h60
  text "REV:" at 3638,-655.67 h60
  text ".PCB_Rev" at 3929.5,-655.67 h60
  text "SVN REV:" at 4476,-655.67 h60
  text ".VersionControl_RevNumber" at 4982,-655.67 h60
  text "TID #:" at 2248,-859 h60
  text ".TID" at 2793.5,-859 h60
  text "PLOT NAME =" at -228.5,-1064.34 h60
  text ".plot_File_Name" at 577,-1064.34 h60
  text "GENERATED    :" at 2250,-1064.34 h60
  text ".Print_Date" at 3119.5,-1064.34 h60
  text ".Print_Time" at 3848.5,-1064.34 h60
  text "TEXAS INSTRUMENTS" at 5113,-1064.34 h60
M6 Assembly Bottom:
  lines w10: -292.5,-727.33 6309.5,-727.33 ; -290.5,-930.67 6309.5,-930.67 ; 1115.5,-1140.5 1115.5,-937.67 ; 1737.5,-727.33 1737.5,-524 ; 2577.5,-727.33 2577.5,-524 ; 3844.5,-1134 3844.5,-524 ; 4733.5,-1134 6309,-1134 6309,-524 -292.5,-524 -292.5,-1134 2304.5,-1134 6309.5,-1134 6309.5,-524
  text "COMPONENTS MARKED 'DNP' SHOULD NOT BE POPULATED." at 6102,-318 h60
  text ".VariantName" at 5058,-434 h60
  text "ASSEMBLY VARIANT:" at 6097,-434 h60
  text ".VersionControl_RevNumber" at 1035.5,-656.17 h60
  text "SVN REV:" at 1541.5,-656.17 h60
  text ".PCB_Rev" at 2088,-656.17 h60
  text "REV:" at 2379.5,-656.17 h60
  text ".PRJ_Number" at 3224,-656.17 h60
  text "BOARD #:" at 3769.5,-656.17 h60
  text "PCB VIEWED FROM BOTTOM SIDE" at 6246,-656.17 h60
  text ".TID" at 3224,-859.5 h60
  text "TID #:" at 3769.5,-859.5 h60
  text "TEXAS INSTRUMENTS" at 904.5,-1064.84 h60
  text ".Print_Time" at 2169,-1064.84 h60
  text ".Print_Date" at 2898,-1064.84 h60
  text "GENERATED    :" at 3767.5,-1064.84 h60
  text ".plot_File_Name" at 5440.5,-1064.84 h60
  text "PLOT NAME =" at 6246,-1064.84 h60
M9 Title Sheet:
  drawing of 57 lines, arcs and shapes, not listed
  text "1" at 739.84,8036.5 h70
  text "2" at 3235.5,8036.5 h70
  text "3" at 5724.84,8036.5 h70
  text "4" at 8231.51,8036.5 h70
  text "5" at 10730.5,8036.5 h70
  text "6" at 13235.5,8036.5 h70
  text "A" at -416.5,6893.5 h70
  text "A" at 14383.5,6893.5 h70
  text "B" at -416.5,4513.5 h70
  text "B" at 14383.5,4513.5 h70
  text "C" at -416.5,2138.5 h70
  text "C" at 14383.5,2138.5 h70
  text "PROJECT TITLE:" at 11343.5,277.5 h45
  text ".PRJ_Title" at 11393.5,144.17 h70
  text "DESIGNED FOR:" at 11343.5,-23.5 h45
  text ".PRJ_Customer" at 11393.5,-163.5 h70
  text "D" at -416.5,-231.5 h70
  text "D" at 14383.5,-231.5 h70
  text "FILE NAME:" at 11343.5,-323.5 h45
  text ".PCB_File_Name_No_Path" at 11393.5,-443.5 h70
  text "Texas Instruments (TI) and/or its licensors do not warrant the accuracy or completeness of this specification" at 6374,-605.34 h45
  text "ENGINEER:" at 11343.5,-613.5 h45
  text "LAYOUT BY:" at 12848.5,-613.5 h45
  text "or any information contained therein. TI and/or its licensors do not warrant that this design will meet" at 6329.01,-718 h45
  text ".PRJ_Engineer" at 11393.5,-768.49 h70
  text ".PCB_Layout" at 12899,-768.49 h70
  text "the specifications, will be suitable for your application or fit for any particular purpose, or will operate in" at 6329.01,-830.67 h45
  text ".Layer_Name" at 577,-858.49 h60
  text "ALTIUM DESIGNER VERSION:" at 12848.5,-923.5 h45
  text "an implementation. TI and/or its licensors do not warrant that the design is production worthy. You should" at 6329.01,-943.33 h45
  text "completely validate and test your design implementation to confirm the system functionality for your application." at 6374,-1056 h45
  text ".print_Scale" at 11393.5,-1056.83 h70
  text ".Application_BuildNumber" at 12899,-1056.83 h70
  text "1" at 739.84,-1263.5 h70
  text "2" at 3235.5,-1263.5 h70
  text "3" at 5724.84,-1263.5 h70
  text "4" at 8231.51,-1263.5 h70
  text "5" at 10730.5,-1263.5 h70
  text "6" at 13235.5,-1263.5 h70
M10 Fab Notes:
  drawing of 173 lines, arcs and shapes, not listed
  text "DESIGN INFORMATION" at 12378.02,6201 h60
  text "MIN. TRACK WIDTH:" at 11733.46,6021 h60
  text "10" at 12829.7,6021 h60
  text "MIL" at 12984.46,6021 h60
  text "MIN. CLEARANCE:" at 11733.46,5889 h60
  text "0.2" at 12769.7,5889 h60
  text "mm" at 12984.46,5889 h60
  text "MIN. VIA PAD SIZE:" at 11733.46,5757 h60
  text "20" at 12799.71,5757 h60
  text "MIL" at 12984.46,5757 h60
  text "0.05mm (2MIL)" at 12428.46,5615.29 h60
  text "MINIMUM ANNULAR RING" at 11404.23,5611 h60
  text "EXTERNAL" at 13136.46,5611 h60
  text "PER" at 11604.23,5493 h60
  text "IPC-D-275 CLASS 2 LEVEL C" at 11824.23,5493 h60
  text "MIL, HOLES" at 13312.46,5380.71 h60
  text "+/-" at 12920,5380 h60
  text "+/-" at 13774,5380 h60
  text "REGISTRATION TOLERANCES:" at 11404.23,5375 h60
  text "METAL" at 12604,5375 h60
  text "5" at 13180.2,5375 h60
  text "3" at 14013.2,5375 h60
  text "MIL" at 14129.46,5375 h60
  text "+/-" at 13774,5262 h60
  text "HOLE SIZE TOLERANCE (UNLESS OTHERWISE SPECIFIED):" at 11404.23,5257 h60
  text "3" at 14013.2,5257 h60
  text "MIL" at 14129.46,5257 h60
  text "MATERIAL:" at 11329.46,5047.54 h60
  text "FR-4 High Tg" at 12315.9,4907.21 h60
  text "FR-408" at 11750.46,4898.64 h60
  text "OTHER" at 13238.46,4898.64 h60
  text "X" at 12161,4895 h60
  text "62 MIL (1.6mm) +/-10%" at 12070.56,4735.92 h60
  text "THICKNESS:" at 11404.23,4731.64 h60
  text "X" at 11942.4,4731.64 h60
  text "OTHER" at 13355.46,4731.64 h60
  text "TOLERANCE:" at 11404.23,4573.64 h60
  text "X" at 12243.53,4573.64 h60
  text "ANSI IPC-6012 TYPE 3 CLASS 2" at 12430.48,4573.64 h60
  text "OTHER +/-" at 12430.46,4417.64 h60
  text "BOW & TWIST:" at 11404.23,4260.64 h60
  text "X" at 12243.53,4260.64 h60
  text "ANSI IPC-6012 TYPE 3 CLASS 2" at 12430.48,4260.64 h60
  text "OTHER +/-" at 12430.46,4102.13 h60
  text "DRILLING:" at 11329.46,3963.64 h60
  text "REFERENCE:" at 11404.23,3846.64 h60
  text "X" at 12052.46,3846.64 h60
  text "AS SHOWN" at 12239.46,3846.64 h60
  text "X" at 12953.46,3846.64 h60
  text "NC_DRILL FILES" at 13090.46,3846.64 h60
  text "PTH COPPER THICKNESS:" at 11404.23,3688.64 h60
  text "X" at 12534.46,3688.64 h60
  text "20-30 um" at 12671.46,3688.64 h60
  text "OTHER" at 13388.46,3688.64 h60
  text "BOARD FINISH:" at 11329.46,3529.64 h60
  text "SILKSCREEN:" at 11484.68,3411.64 h60
  text "X" at 12433.46,3411.64 h60
  text "TOP" at 12559.46,3411.64 h60
  text "X" at 12943.46,3411.64 h60
  text "BOTTOM" at 13070.46,3411.64 h60
  text "SILKSCREEN COLOR:" at 11484.68,3244.64 h60
  text "X" at 12432.42,3244.64 h60
  text "WHITE" at 12559.46,3244.64 h60
  text "OTHER" at 13070.46,3244.64 h60
  text "X" at 12563.42,3085.44 h60
  text "GREEN" at 12690.46,3085.44 h60
  text "OTHER" at 13308.46,3085.44 h60
  text "SOLDER RESIST COLOR:" at 11484.68,3074.64 h60
  text "X" at 12563.42,2915.44 h60
  text "MATTE" at 12690.46,2915.44 h60
  text "SEMI-GLOSS" at 13308,2914.8 h60
  text "IMMERSION GOLD (ENIG)" at 12390.46,2726.92 h60
  text "ENEPIG" at 13728,2723.64 h60
  text "SURFACE FINISH:" at 11329.46,2722.64 h60
  text "X" at 11500,2570 h60
  text "IMM. TIN/SILVER OR EQUIV" at 11659,2565.64 h60
  text "OTHER" at 13090.46,2565.64 h60
  text "ARRAY/PANEL:" at 11329.46,2386.64 h60
  text "CUT AND TRIM PER M1 BOARD OUTLINE" at 12390.46,2382.35 h60
  text "N.C. ROUTE" at 12390.46,2230.64 h60
  text "X" at 13069.46,2230.64 h60
  text "V. SCORE" at 13256.46,2230.64 h60
  text "CERTIFICATION:" at 11329.46,2093.64 h60
  text "MATERIALS AND WORKMANSHIP FOR ALL PCBS" at 12054.46,2093.64 h60
  text "TO MEET OR EXCEED THE REQUIREMENTS OF:" at 12054.46,1995.64 h60
  text "X" at 11680.96,1859.13 h60
  text "ANSI IPC-A-600F CLASS ->" at 11819.96,1859.13 h60
  text "X" at 13459.02,1859.13 h60
  text "2" at 13577.96,1859.14 h60
  text "1" at 13262.96,1857.64 h60
  text "3" at 13931.96,1857.64 h60
  text "X" at 12495.02,1699.64 h60
  text "RoHS" at 12631.96,1699.64 h60
  text "OTHER" at 13276.36,1699.64 h60
  text "PER ORDER" at 13673.42,1699.64 h60
  text "ALL BOARDS MUST MEET OR EXCEED UL94-V0 REQUIREMENTS." at 11357,1534 h60
  text "PCB MUST BEAR THE UL94V-0 UL REGISTERED MATERIAL ID NUMBER" at 11357,1414 h60
  text "ADDITIONAL REQUIREMENTS:" at 11329.46,1240.64 h60
  text "MICROSECTION:" at 11404.23,1125.64 h60
  text "YES" at 12309.96,1125.64 h60
  text "X" at 12590,970 h60
  text "REQUIRED" at 13171.46,969.49 h60
  text "BARE BOARD ELEC. TEST:" at 11404.23,966.64 h60
  text "NONE" at 12709.96,966.64 h60
  text "PER ORDER" at 13763.46,966.64 h60
  text ".Layer_Name" at 577,-858.49 h60
M11 Gerber Information:
  lines w10: -292,-930.17 6308,-930.17 ; -292,-726.83 6310,-726.83 ; -292,-523.5 -292,-1133.5 3713,-1133.5 6310,-1133.5 6310,-523.5 -291.5,-523.5 -291.5,-1133.5 1284,-1133.5 ; 2173,-1133.5 2173,-523.5 ; 3440,-726.83 3440,-523.5 ; 4280,-726.83 4280,-523.5 ; 4902,-1140 4902,-937.17
  text "ALL ARTWORK VIEWED FROM TOP SIDE" at -228.5,-655.67 h60
  text "BOARD #:" at 2248,-655.67 h60
  text ".PRJ_Number" at 2793.5,-655.67 h60
  text "REV:" at 3638,-655.67 h60
  text ".PCB_Rev" at 3929.5,-655.67 h60
  text "SVN REV:" at 4476,-655.67 h60
  text ".VersionControl_RevNumber" at 4982,-655.67 h60
  text "LAYER NAME =" at -228.5,-858.49 h60
  text "TID #:" at 2248,-859 h60
  text ".TID" at 2793.5,-859 h60
  text "PLOT NAME =" at -228.5,-1064.34 h60
  text ".plot_File_Name" at 577,-1064.34 h60
  text "GENERATED    :" at 2250,-1064.34 h60
  text ".Print_Date" at 3119.5,-1064.34 h60
  text ".Print_Time" at 3848.5,-1064.34 h60
  text "TEXAS INSTRUMENTS" at 5113,-1064.34 h60
M12 Stackup:
  drawing of 191 lines, arcs and shapes, not listed
  text "Layer" at 9790.34,7830 h60
  text "Name" at 10200.26,7830 h60
  text "Material" at 11130,7830 h60
  text "Thickness" at 11989.77,7830 h60
  text "Constant" at 12639.6,7830 h60
  text "Board Layer Stack" at 13209.46,7830 h60
  text "1" at 9790.34,7710 h60
  text "Top Overlay" at 10200.26,7710 h60
  text "2" at 9790.34,7590 h60
  text "Top Solder" at 10200.26,7590 h60
  text "Solder Resist" at 11130,7590 h60
  text "0.40mil" at 11989.77,7590 h60
  text "3.5" at 12639.6,7590 h60
  text "3" at 9790.34,7470 h60
  text "Top Layer" at 10200.26,7470 h60
  text "Copper" at 11130,7470 h60
  text "1.40mil" at 11989.77,7470 h60
  text "4" at 9790.34,7350 h60
  text "Dielectric1" at 10200.26,7350 h60
  text "FR-4" at 11130,7350 h60
  text "59.20mil" at 11989.77,7350 h60
  text "4.8" at 12639.6,7350 h60
  text "5" at 9790.34,7230 h60
  text "Bottom Layer" at 10200.26,7230 h60
  text "Copper" at 11130,7230 h60
  text "1.40mil" at 11989.77,7230 h60
  text "6" at 9790.34,7110 h60
  text "Bottom Solder" at 10200.26,7110 h60
  text "Solder Resist" at 11130,7110 h60
  text "0.40mil" at 11989.77,7110 h60
  text "3.5" at 12639.6,7110 h60
  text "7" at 9790.34,6990 h60
  text "Bottom Overlay" at 10200.26,6990 h60
  text ".Layer_Name" at 577,-858.49 h60
M13 Component Bodies Top:
  text ".Layer_Name" at 577,-858.49 h60
M14 Component Bodies Bottom:
  text ".Layer_Name" at 577,-858.49 h60
M15 Courtyards Top:
  text ".Layer_Name" at 577,-858.49 h60
M16 Courtyards Bottom:
  text ".Layer_Name" at 577,-858.49 h60
Drill Drawing:
  drawing of 180 lines, arcs and shapes, not listed
  text "Symbol" at 0.59,7712.98 h72
  text "Quantity" at 301.16,7712.98 h72
  text "Finished Hole Size" at 633.16,7712.98 h72
  text "Plated" at 1269.72,7712.98 h72
  text "Hole Type" at 1528.86,7712.98 h72
  text "Drill Layer Pair" at 1904.02,7712.98 h72
  text "Hole Tolerance" at 2628.35,7712.98 h72
  text "118" at 301.16,7588.66 h60
  text "0.254mm (10.00mil)" at 633.16,7588.66 h60
  text "PTH" at 1269.72,7588.66 h60
  text "Round" at 1528.86,7588.66 h60
  text "Top Layer - Bottom Layer" at 1904.02,7588.66 h60
  text "G" at -24.69,7578.67 h55.25
  text "8" at 301.16,7464.34 h60
  text "0.650mm (25.59mil)" at 633.16,7464.34 h60
  text "PTH" at 1269.72,7464.34 h60
  text "Round" at 1528.86,7464.34 h60
  text "Top Layer - Bottom Layer" at 1904.02,7464.34 h60
  text "C" at -24.69,7454.34 h55.25
  text "2" at 301.16,7340.02 h60
  text "0.750mm (29.53mil)" at 633.16,7340.02 h60
  text "PTH" at 1269.72,7340.02 h60
  text "Round" at 1528.86,7340.02 h60
  text "Top Layer - Bottom Layer" at 1904.02,7340.02 h60
  text "14" at 301.16,7215.7 h60
  text "0.850mm (33.46mil)" at 633.16,7215.7 h60
  text "PTH" at 1269.72,7215.7 h60
  text "Round" at 1528.86,7215.7 h60
  text "Top Layer - Bottom Layer" at 1904.02,7215.7 h60
  text "4" at 301.16,7091.38 h60
  text "0.900mm (35.43mil)" at 633.16,7091.38 h60
  text "PTH" at 1269.72,7091.38 h60
  text "Round" at 1528.86,7091.38 h60
  text "Top Layer - Bottom Layer" at 1904.02,7091.38 h60
  text "2" at 301.16,6967.06 h60
  text "1.000mm (39.37mil)" at 633.16,6967.06 h60
  text "PTH" at 1269.72,6967.06 h60
  text "Round" at 1528.86,6967.06 h60
  text "Top Layer - Bottom Layer" at 1904.02,6967.06 h60
  text "2" at 301.16,6842.74 h60
  text "1.016mm (40.00mil)" at 633.16,6842.74 h60
  text "PTH" at 1269.72,6842.74 h60
  text "Round" at 1528.86,6842.74 h60
  text "Top Layer - Bottom Layer" at 1904.02,6842.74 h60
  text "A" at -24.69,6832.75 h55.25
  text "4" at 301.16,6718.42 h60
  text "1.050mm (41.34mil)" at 633.16,6718.42 h60
  text "PTH" at 1269.72,6718.42 h60
  text "Round" at 1528.86,6718.42 h60
  text "Top Layer - Bottom Layer" at 1904.02,6718.42 h60
  text "8" at 301.16,6594.1 h60
  text "1.100mm (43.31mil)" at 633.16,6594.1 h60
  text "PTH" at 1269.72,6594.1 h60
  text "Round" at 1528.86,6594.1 h60
  text "Top Layer - Bottom Layer" at 1904.02,6594.1 h60
  text "9" at 301.16,6469.78 h60
  text "1.170mm (46.06mil)" at 633.16,6469.78 h60
  text "PTH" at 1269.72,6469.78 h60
  text "Round" at 1528.86,6469.78 h60
  text "Top Layer - Bottom Layer" at 1904.02,6469.78 h60
  text "F" at -24.69,6459.78 h55.25
  text "6" at 301.16,6345.46 h60
  text "1.270mm (50.00mil)" at 633.16,6345.46 h60
  text "PTH" at 1269.72,6345.46 h60
  text "Round" at 1528.86,6345.46 h60
  text "Top Layer - Bottom Layer" at 1904.02,6345.46 h60
  text "14" at 301.16,6221.14 h60
  text "1.300mm (51.18mil)" at 633.16,6221.14 h60
  text "PTH" at 1269.72,6221.14 h60
  text "Round" at 1528.86,6221.14 h60
  text "Top Layer - Bottom Layer" at 1904.02,6221.14 h60
  text "4" at 301.16,6096.82 h60
  text "1.321mm (52.00mil)" at 633.16,6096.82 h60
  text "PTH" at 1269.72,6096.82 h60
  text "Round" at 1528.86,6096.82 h60
  text "Top Layer - Bottom Layer" at 1904.02,6096.82 h60
  text "6" at 301.16,5972.5 h60
  text "1.400mm (55.12mil)" at 633.16,5972.5 h60
  text "PTH" at 1269.72,5972.5 h60
  text "Round" at 1528.86,5972.5 h60
  text "Top Layer - Bottom Layer" at 1904.02,5972.5 h60
  text "4" at 301.16,5848.18 h60
  text "1.500mm (59.06mil)" at 633.16,5848.18 h60
  text "PTH" at 1269.72,5848.18 h60
  text "Round" at 1528.86,5848.18 h60
  text "Top Layer - Bottom Layer" at 1904.02,5848.18 h60
  text "8" at 301.16,5723.86 h60
  text "1.600mm (62.99mil)" at 633.16,5723.86 h60
  text "PTH" at 1269.72,5723.86 h60
  text "Round" at 1528.86,5723.86 h60
  text "Top Layer - Bottom Layer" at 1904.02,5723.86 h60
  text "2" at 301.16,5599.54 h60
  text "2.000mm (78.74mil)" at 633.16,5599.54 h60
  text "PTH" at 1269.72,5599.54 h60
  text "Round" at 1528.86,5599.54 h60
  text "Top Layer - Bottom Layer" at 1904.02,5599.54 h60
  text "3" at 301.16,5475.22 h60
  text "2.032mm (80.00mil)" at 633.16,5475.22 h60
  text "PTH" at 1269.72,5475.22 h60
  text "Round" at 1528.86,5475.22 h60
  text "Top Layer - Bottom Layer" at 1904.02,5475.22 h60
  text "E" at -24.69,5465.23 h55.25
  text "3" at 301.16,5350.9 h60
  text "2.150mm (84.65mil)" at 633.16,5350.9 h60
  text "PTH" at 1269.72,5350.9 h60
  text "Round" at 1528.86,5350.9 h60
  text "Top Layer - Bottom Layer" at 1904.02,5350.9 h60
  text "4" at 301.16,5226.58 h60
  text "2.670mm (105.12mil)" at 633.16,5226.58 h60
  text "PTH" at 1269.72,5226.58 h60
  text "Round" at 1528.86,5226.58 h60
  text "Top Layer - Bottom Layer" at 1904.02,5226.58 h60
  text "D" at -24.69,5216.59 h55.25
  text "225 Total" at 301.16,5102.26 h60
  text ".Layer_Name" at 577,-858.49 h60
M17 Embedded Cavity:
  text ".Layer_Name" at 577,-858.49 h60
M18 Embedded Assembly:
  text ".Layer_Name" at 577,-858.49 h60
M19 Embedded Keepout:
  text ".Layer_Name" at 577,-858.49 h60

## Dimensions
0,0 to 7086.61,0 on M2 Board Dimensions
0,0 to 0,2677.17 on M2 Board Dimensions
0,-400 to 1000,-400 on M2 Board Dimensions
